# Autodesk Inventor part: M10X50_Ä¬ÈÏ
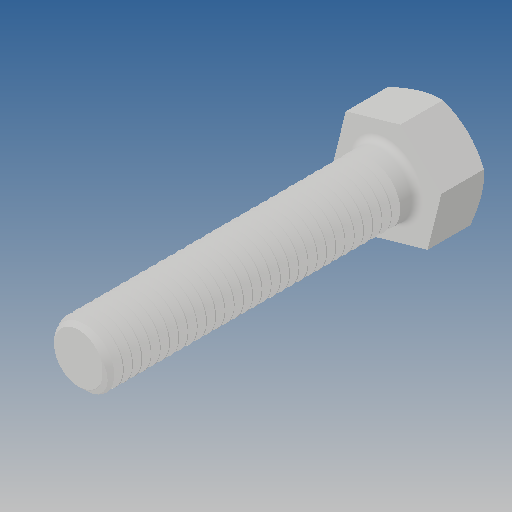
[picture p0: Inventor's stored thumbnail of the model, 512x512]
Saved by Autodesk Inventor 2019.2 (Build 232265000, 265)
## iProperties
Created: 2010-06
Part Number: M10X50_Ä¬ÈÏ
Material: Ogólny
Document SubType Name: Modeling
Designer: CADENGINEERING4
Density: 1 g/cm^3
Appearance: Domyślna
Author: CADENGINEERING4
Revision Number: ÈÎºÎ
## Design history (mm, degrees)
feature "NONE"
node "Bryła1"
